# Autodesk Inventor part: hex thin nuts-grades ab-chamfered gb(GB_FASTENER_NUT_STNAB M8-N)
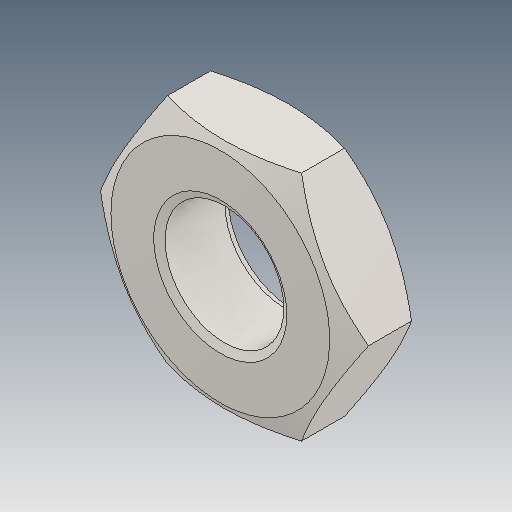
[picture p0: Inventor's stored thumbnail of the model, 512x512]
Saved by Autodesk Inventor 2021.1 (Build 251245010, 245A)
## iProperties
Created: 2021-05
Part Number: hex thin nuts-grades ab-chamfered gb(GB_FASTENER_NUT_STNAB M8-N)
Material: Ogólny
Document SubType Name: Modeling
Designer: user
Density: 1 g/cm^3
Appearance: Domyślna
Author: user
Revision Number: ÈÎºÎ
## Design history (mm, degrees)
feature "ÊäÈë1"
node "Bryła1"
